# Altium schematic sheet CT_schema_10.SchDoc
size 281 x 153 mm
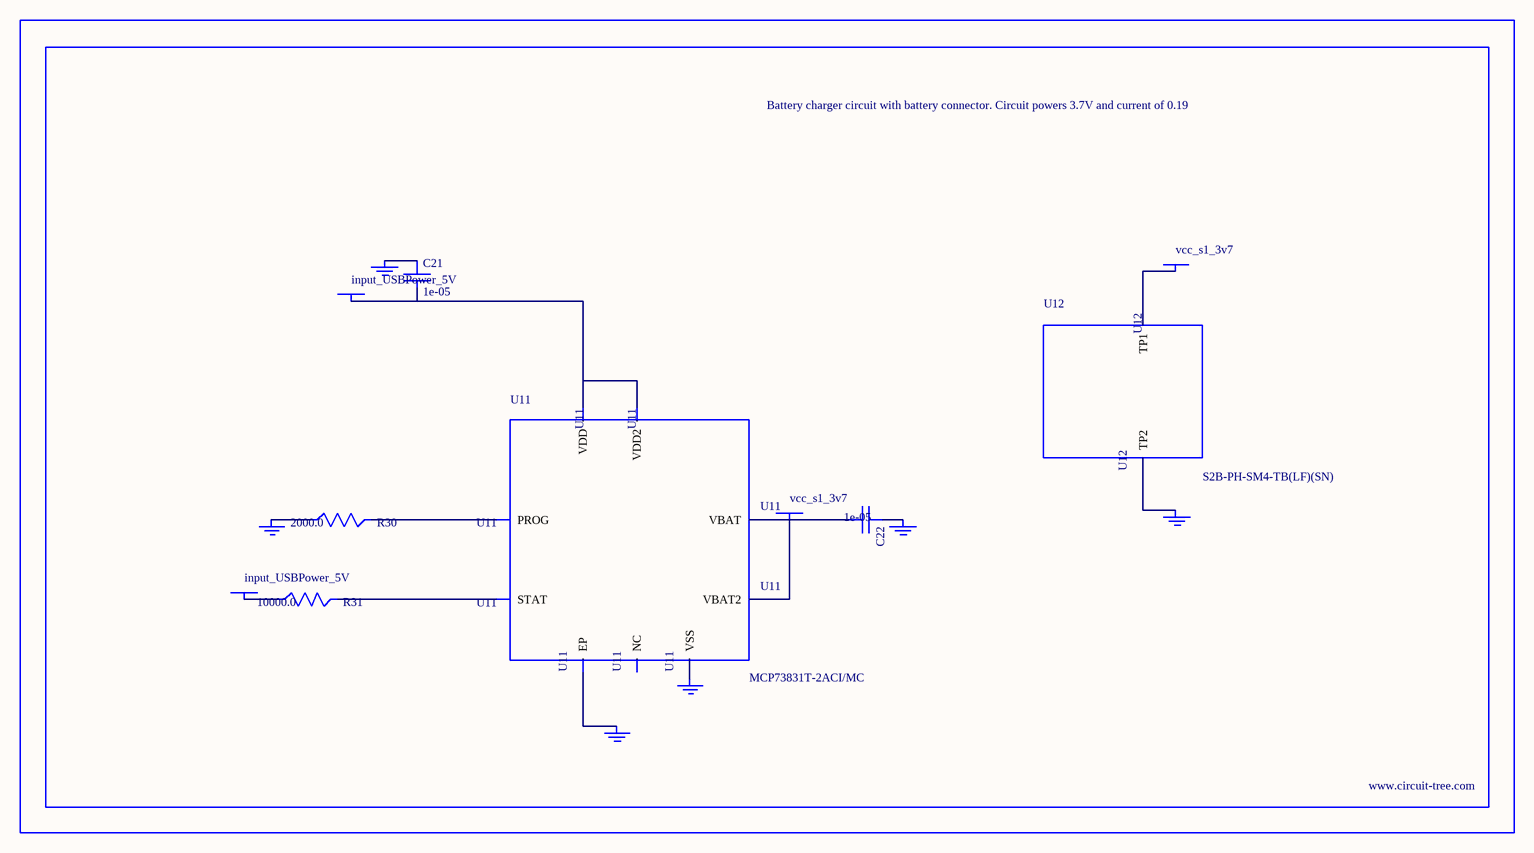
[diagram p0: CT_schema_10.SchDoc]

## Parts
BORDER9  (no value)
C21  1e-05  [C1206]
C22  1e-05  [C1206]
GND_INSTANCE_9_0  (no value)
GND_INSTANCE_9_1  (no value)
GND_INSTANCE_9_2  (no value)
GND_INSTANCE_9_3  (no value)
GND_INSTANCE_9_4  (no value)
GND_INSTANCE_9_5  (no value)
POWER_INSTANCE_9_0  input_USBPower_5V
POWER_INSTANCE_9_1  input_USBPower_5V
POWER_INSTANCE_9_2  vcc_s1_3v7
POWER_INSTANCE_9_3  vcc_s1_3v7
R30  2000.0  [R0603]
R31  10000.0  [R0603]
U11  MCP73831T-2ACI/MC  [DFN8_2X3MC]
U12  S2B-PH-SM4-TB(LF)(SN)  [JST-2-SMD]

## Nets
NetC21_1: C21.1 GND_INSTANCE_9_0.0(GND)
NetC21_2: C21.2 POWER_INSTANCE_9_0.0(PWR) U11.1(VDD) U11.2(VDD2)
NetC22_1: C22.1 GND_INSTANCE_9_1.0(GND)
NetC22_2: C22.2 POWER_INSTANCE_9_2.0(PWR) U11.3(VBAT) U11.4(VBAT2)
NetGND_INSTANCE_9_2_0: GND_INSTANCE_9_2.0(GND) R30.1
NetGND_INSTANCE_9_3_0: GND_INSTANCE_9_3.0(GND) U11.9(EP)
NetGND_INSTANCE_9_4_0: GND_INSTANCE_9_4.0(GND) U11.6(VSS)
NetGND_INSTANCE_9_5_0: GND_INSTANCE_9_5.0(GND) U12.2(TP2)
NetPOWER_INSTANCE_9_1_0: POWER_INSTANCE_9_1.0(PWR) R31.1
NetPOWER_INSTANCE_9_3_0: POWER_INSTANCE_9_3.0(PWR) U12.1(TP1)
NetR30_2: R30.2 U11.8(PROG)
NetR31_2: R31.2 U11.5(STAT)

Not connected (* = marked no-connect by the designer): U11 7(NC)

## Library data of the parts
BORDER9 = BORDER_PAGE9
C21 C22 = C1206C106K3RACTU
GND_INSTANCE_9_0-GND_INSTANCE_9_5 = GND
POWER_INSTANCE_9_0-POWER_INSTANCE_9_3 = PWR
R30 = RC0603JR-072KL
R31 = RC0603JR-0710KL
